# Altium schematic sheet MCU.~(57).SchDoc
size A3; SheetNumber: 10; SheetTotal: 11
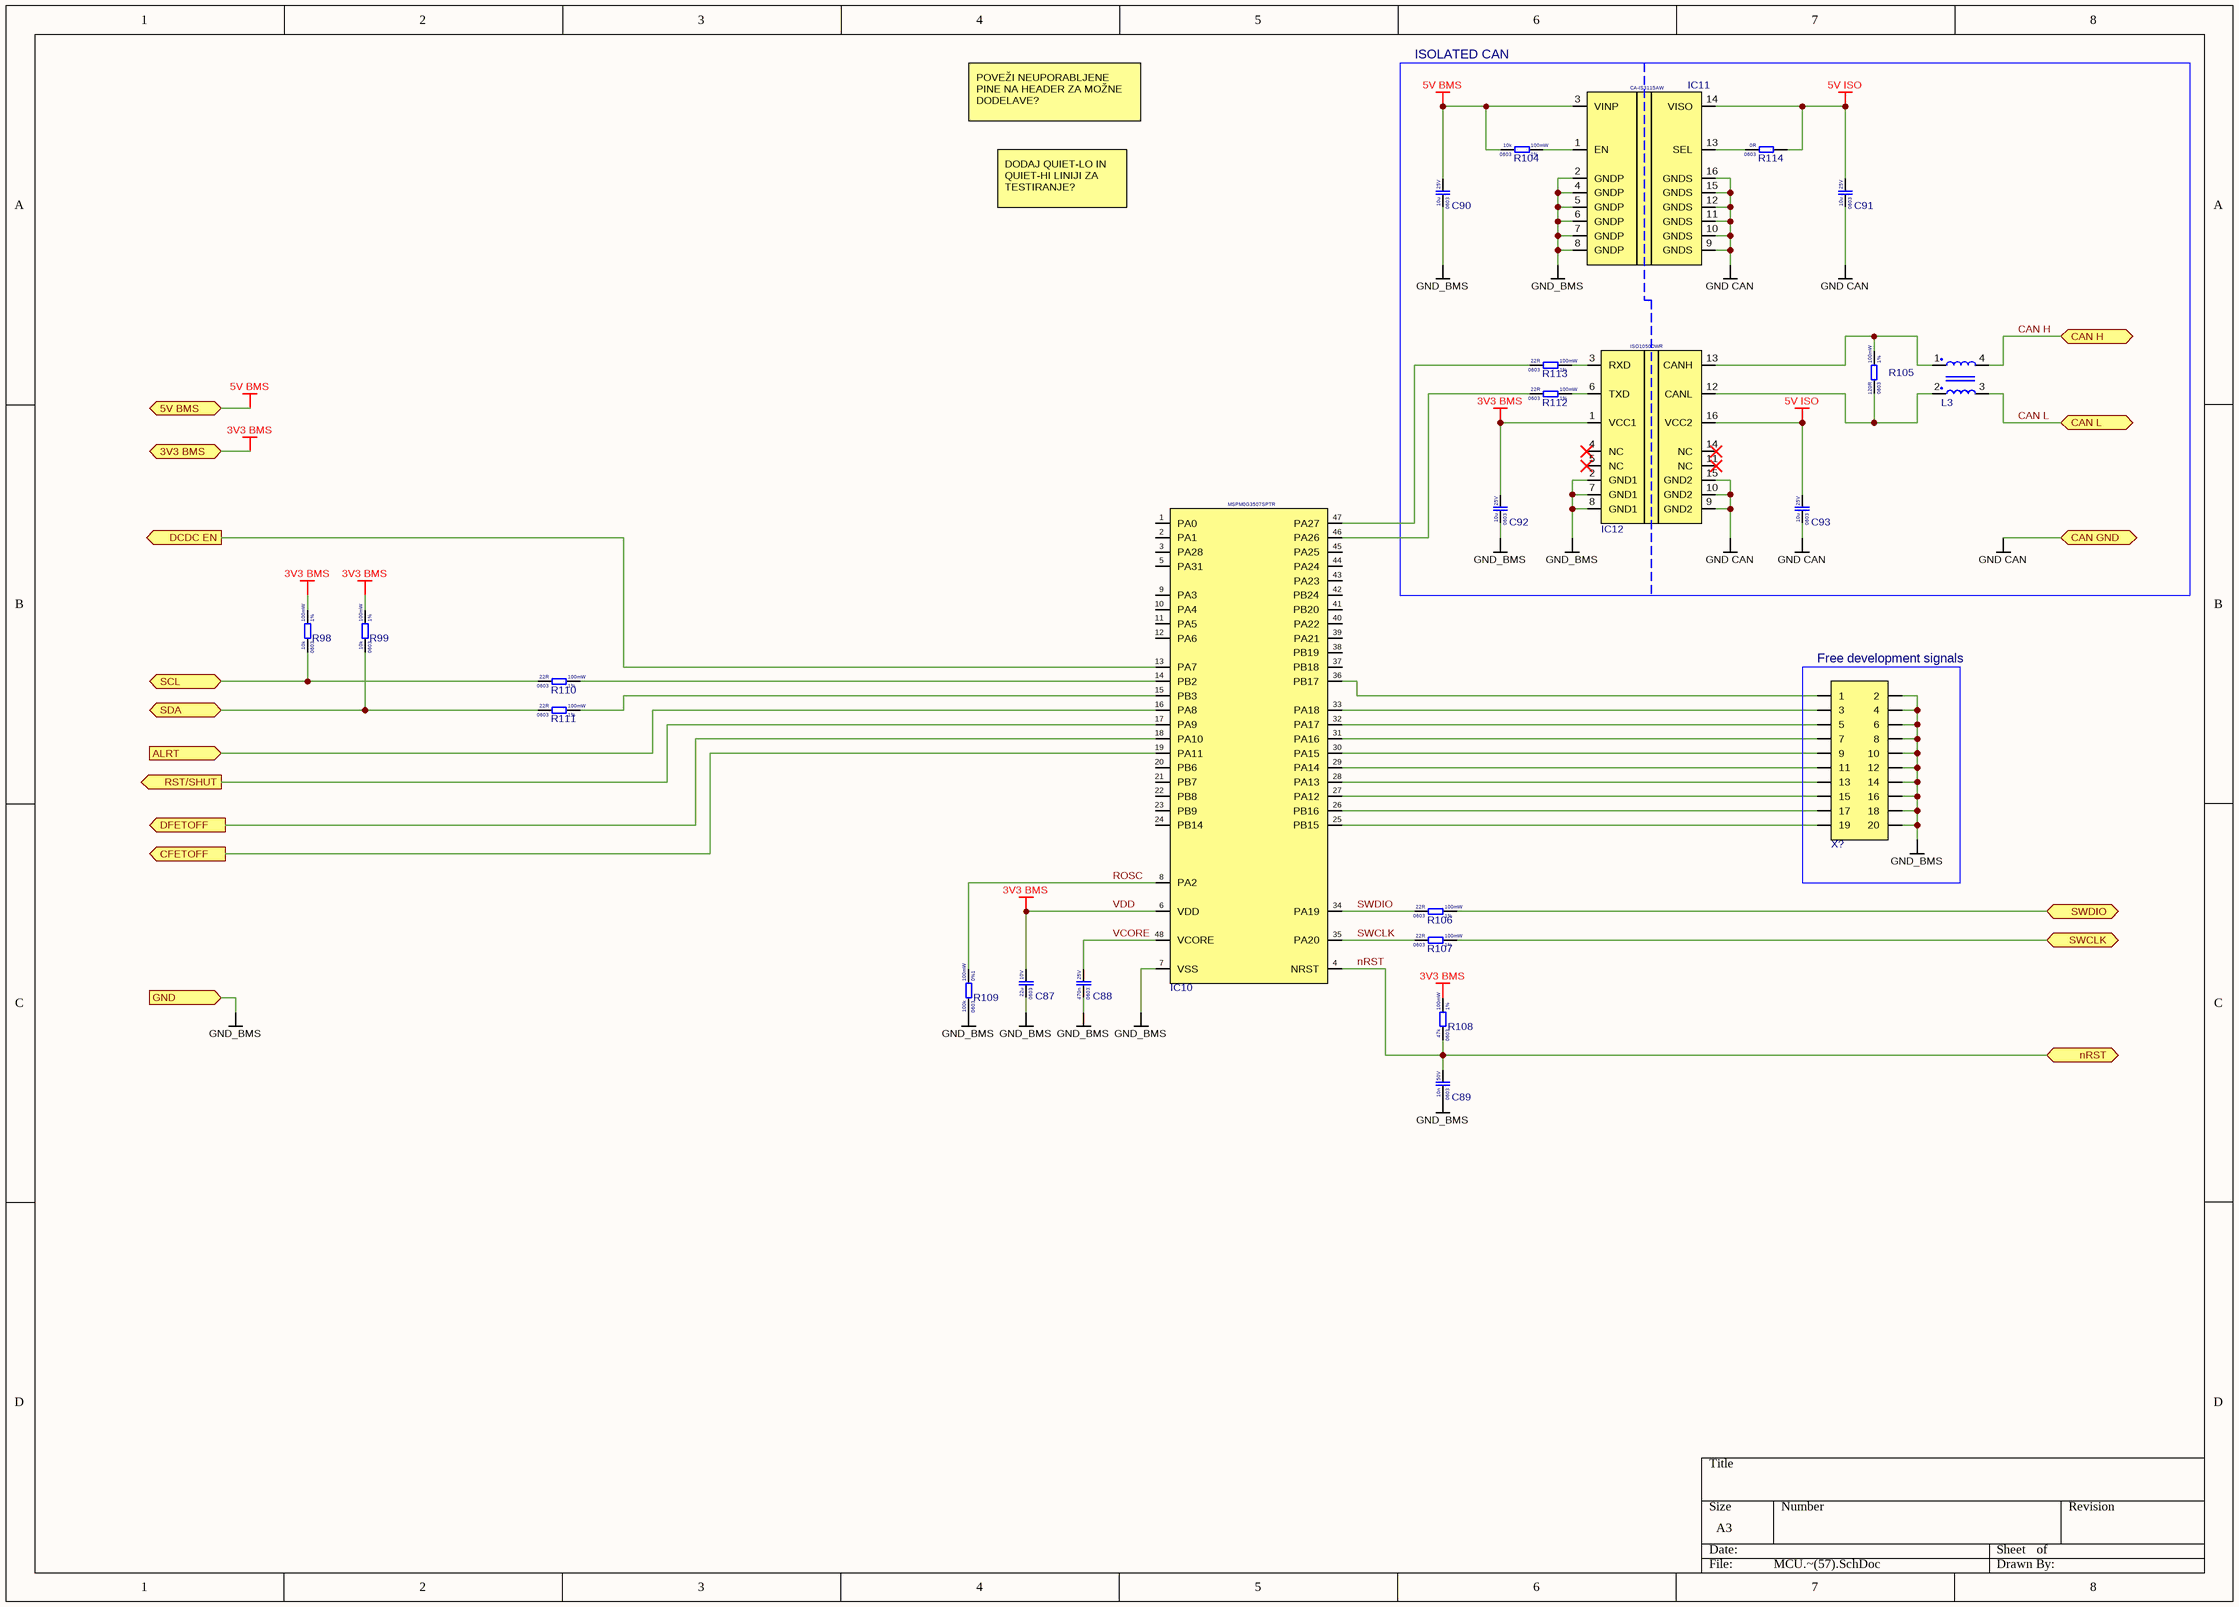
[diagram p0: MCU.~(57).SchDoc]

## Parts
C87  Voltage Rating: 10V  Case Code (Imperial): 0603  Capacitance: 22u  [CAP 0603]  (hidden comment: CGA0603X5R226M100JT)
C88  Voltage Rating: 25V  Case Code (Imperial): 0603  Capacitance: 470n  [CAP 0603]  (hidden comment: CL10B474KA8NNNC)
C89  Voltage Rating: 50V  Case Code (Imperial): 0603  Capacitance: 10n  [CAP 0603]  (hidden comment: 0603B103K500NT)
C90  Voltage Rating: 25V  Case Code (Imperial): 0603  Capacitance: 10u  [CAP 0603]  (hidden comment: CL10A106MA8NRNC)
C91  Voltage Rating: 25V  Case Code (Imperial): 0603  Capacitance: 10u  [CAP 0603]  (hidden comment: CL10A106MA8NRNC)
C92  Voltage Rating: 25V  Case Code (Imperial): 0603  Capacitance: 10u  [CAP 0603]  (hidden comment: CL10A106MA8NRNC)
C93  Voltage Rating: 25V  Case Code (Imperial): 0603  Capacitance: 10u  [CAP 0603]  (hidden comment: CL10A106MA8NRNC)
IC10  MSPM0G3507SPTR  [LQFP-48]
IC11  CA-IS3115AW  [SOIC-16-WB]
IC12  ISO1050DWR  [SOIC-16-WB]
L3  ACM2012-900-2P-T002  [ACM2012-900-2P-T002]  (value not drawn)
R98  Resistance Tolerance: 1%  Resistance: 10k  Power Rating: 100mW  Case Code (Imperial): 0603  [RES_0603]  (hidden comment: 0603WAF1002T5E)
R99  Resistance Tolerance: 1%  Resistance: 10k  Power Rating: 100mW  Case Code (Imperial): 0603  [RES_0603]  (hidden comment: 0603WAF1002T5E)
R104  Resistance Tolerance: 1%  Resistance: 10k  Power Rating: 100mW  Case Code (Imperial): 0603  [RES_0603]  (hidden comment: 0603WAF1002T5E)
R105  Resistance Tolerance: 1%  Resistance: 120R  Power Rating: 100mW  Case Code (Imperial): 0603  [RES_0603]  (hidden comment: 0603WAF1200T5E)
R106  Resistance Tolerance: 1%  Resistance: 22R  Power Rating: 100mW  Case Code (Imperial): 0603  [RES_0603]  (hidden comment: 0603WAF220JT5E)
R107  Resistance Tolerance: 1%  Resistance: 22R  Power Rating: 100mW  Case Code (Imperial): 0603  [RES_0603]  (hidden comment: 0603WAF220JT5E)
R108  Resistance Tolerance: 1%  Resistance: 47k  Power Rating: 100mW  Case Code (Imperial): 0603  [RES_0603]  (hidden comment: 0603WAF4702T5E)
R109  Resistance Tolerance: 0%1  Resistance: 100k  Power Rating: 100mW  Case Code (Imperial): 0603  [RES_0603]  (hidden comment: RT0603BRD07100KL)
R110  Resistance Tolerance: 1%  Resistance: 22R  Power Rating: 100mW  Case Code (Imperial): 0603  [RES_0603]  (hidden comment: 0603WAF220JT5E)
R111  Resistance Tolerance: 1%  Resistance: 22R  Power Rating: 100mW  Case Code (Imperial): 0603  [RES_0603]  (hidden comment: 0603WAF220JT5E)
R112  Resistance Tolerance: 1%  Resistance: 22R  Power Rating: 100mW  Case Code (Imperial): 0603  [RES_0603]  (hidden comment: 0603WAF220JT5E)
R113  Resistance Tolerance: 1%  Resistance: 22R  Power Rating: 100mW  Case Code (Imperial): 0603  [RES_0603]  (hidden comment: 0603WAF220JT5E)
R114  Resistance: 0R  Case Code (Imperial): 0603  [RES_0603]  (hidden comment: 0603WAF0000T5E)
X?  PZ254V-12-20P  [Pin header 2x10 2.54mm THT Vertical]  (value not drawn)

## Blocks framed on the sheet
ISOLATED CAN: C90-C93 IC11 IC12 L3 R104 R105 R112-R114
Free development signals: X?

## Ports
3V3 BMS (bidir, see BMS[4B]), 5V BMS (bidir, see BMS[4B]), ALRT (in, see BMS[4B], BQ76952 BMS[7C]), CAN GND (bidir, see BMS[4B], BMS[8B]), CAN H (bidir, see BMS[4B], BMS[8B], ESD system side[2B]), CAN L (bidir, see BMS[4B], BMS[8B], ESD system side[2B]), CFETOFF (out, see BMS[4B], BQ76952 BMS[7C]), DCDC EN (out, see BMS[4B]), DFETOFF (out, see BMS[4B], BQ76952 BMS[7C]), GND (in, see BMS[4C], BQ76952 BMS[1D]), nRST (bidir, see BMS[4B], BMS[8B]), RST/SHUT (out, see BMS[4B], BQ76952 BMS[7C]), SCL (bidir, see BMS[4C], BMS[8C], BQ76952 BMS[7C]), SDA (bidir, see BMS[4C], BMS[8C], BQ76952 BMS[7C]), SWCLK (bidir, see BMS[4B], BMS[8B]), SWDIO (bidir, see BMS[4B], BMS[8B])

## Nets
5V BMS: C90.2 IC11.3(VINP) R104.1 ; port 5V BMS
5V ISO: C91.2 C93.2 IC11.14(VISO) IC12.16(VCC2) R114.2
GND CAN: C91.1 C93.1 IC11.9(GNDS) IC11.10(GNDS) IC11.11(GNDS) IC11.12(GNDS) IC11.15(GNDS) IC11.16(GNDS) IC12.9(GND2) IC12.10(GND2) IC12.15(GND2) ; port CAN GND
GND_BMS: C87.1 C88.1 C89.1 C90.1 C92.1 IC10.7(VSS) IC11.2(GNDP) IC11.4(GNDP) IC11.5(GNDP) IC11.6(GNDP) IC11.7(GNDP) IC11.8(GNDP) IC12.2(GND1) IC12.7(GND1) IC12.8(GND1) R109.1 X?.2 X?.4 X?.6 X?.8 X?.10 X?.12 X?.14 X?.16 X?.18 X?.20 ; port GND
VDD: C87.2 C92.2 IC10.6(VDD) IC12.1(VCC1) R98.2 R99.2 R108.2 ; port 3V3 BMS  [also labelled 3V3 BMS]
ALRT: IC10.16(PA8) ; port ALRT
CAN H: L3.4 ; port CAN H
CAN L: L3.3 ; port CAN L
CFETOFF: IC10.19(PA11) ; port CFETOFF
DCDC EN: IC10.13(PA7) ; port DCDC EN
DFETOFF: IC10.18(PA10) ; port DFETOFF
nRST: C89.2 IC10.4(NRST) R108.1 ; port nRST
ROSC: IC10.8(PA2) R109.2
RST/SHUT: IC10.17(PA9) ; port RST/SHUT
SCL: R98.1 R110.1 ; port SCL
SDA: R99.1 R111.1 ; port SDA
SWCLK: IC10.35(PA20) R107.1
SWCLK: R107.2 ; port SWCLK  [a separate net that carries the same name]
SWDIO: IC10.34(PA19) R106.1
SWDIO: R106.2 ; port SWDIO  [a separate net that carries the same name]
VCORE: C88.2 IC10.48(VCORE)
NetIC10_14: IC10.14(PB2) R110.2
NetIC10_15: IC10.15(PB3) R111.2
NetIC10_25: IC10.25(PB15) X?.19
NetIC10_26: IC10.26(PB16) X?.17
NetIC10_27: IC10.27(PA12) X?.15
NetIC10_28: IC10.28(PA13) X?.13
NetIC10_29: IC10.29(PA14) X?.11
NetIC10_30: IC10.30(PA15) X?.9
NetIC10_31: IC10.31(PA16) X?.7
NetIC10_32: IC10.32(PA17) X?.5
NetIC10_33: IC10.33(PA18) X?.3
NetIC10_36: IC10.36(PB17) X?.1
NetIC10_46: IC10.46(PA26) R112.1
NetIC10_47: IC10.47(PA27) R113.1
NetIC11_1: IC11.1(EN) R104.2
NetIC11_13: IC11.13(SEL) R114.1
NetIC12_3: IC12.3(RXD) R113.2
NetIC12_6: IC12.6(TXD) R112.2
NetIC12_12: IC12.12(CANL) L3.2 R105.1
NetIC12_13: IC12.13(CANH) L3.1 R105.2

Not connected (* = marked no-connect by the designer): IC10 1(PA0) 2(PA1) 3(PA28) 5(PA31) 9(PA3) 10(PA4) 11(PA5) 12(PA6) 20(PB6) 21(PB7) 22(PB8) 23(PB9) 24(PB14) 37(PB18) 38(PB19) 39(PA21) 40(PA22) 41(PB20) 42(PB24) 43(PA23) 44(PA24) 45(PA25); IC12 4(NC)* 5(NC)* 11(NC)* 14(NC)*

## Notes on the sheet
- POVEŽI NEUPORABLJENE PINE NA HEADER ZA MOŽNE DODELAVE?
- DODAJ QUIET-LO IN QUIET-HI LINIJI ZA TESTIRANJE?

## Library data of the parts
C87 = CGA0603X5R226M100JT: Cap 22uF 10V 0603 X5R; Manufacturer: HRE
C88 = CL10B474KA8NNNC: Cap 470nF 25V 0603 X7R; Manufacturer: Samsung
C89 = 0603B103K500NT: Cap 10nF 50V 0603 X7R; Manufacturer: FH
C90-C93 = CL10A106MA8NRNC: Cap 10uF 25V 0603 X5R; Manufacturer: Samsung
IC10 = MSPM0G3507SPTR: MCU MSPM0G3507SPTR LQFP-48; Manufacturer: Texas Instruments
IC11 = CA-IS3115AW: DCDC Module Isolated 5Vin 5Vout 1.5W SOIC-16-WB; Manufacturer: Chipanalog
IC12 = ISO1050DWR: CAN ISO transciever SOIC-16-WB; Manufacturer: Texas Instruments
L3 = ACM2012-900-2P-T002: CMC 90R@100MHz 190mR 400mA 50V; Manufacturer: TDK
R98 R99 R104 = 0603WAF1002T5E: Res 10k 0603 1% 100mW 75V; Manufacturer: Uni-Royal
R105 = 0603WAF1200T5E: Res 120R 0603 1% 100mW 75V; Manufacturer: Uni-Royal; Manufacturer Part Number: 0603WAF5101T5E
R106 R107 R110-R113 = 0603WAF220JT5E: Res 22R 0603 1% 100mW 75V; Manufacturer: Uni-Royal
R108 = 0603WAF4702T5E: Res 47k 0603 1% 100mW 75V; Manufacturer: Uni-Royal
R109 = RT0603BRD07100KL: Res 100k 0603 0.1% 100mW 75V 25ppm; Manufacturer: YAGEO
R114 = 0603WAF0000T5E: Res 0R 0603 1% 100mW 75V; Manufacturer: UNI-ROYAL
X? = PZ254V-12-20P: Pin header 2x10 2.54mm THT Vertical; Manufacturer: XFCN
